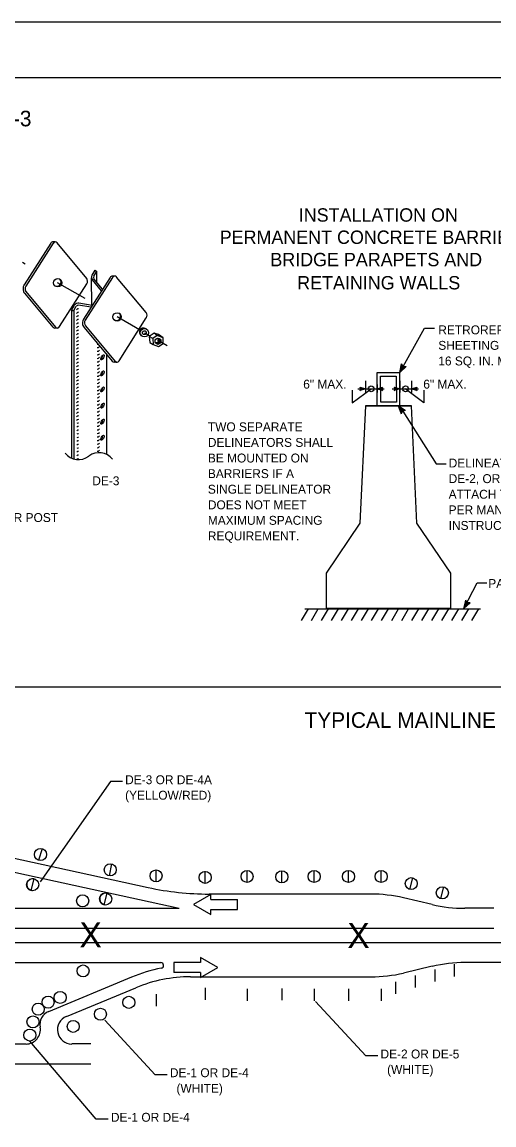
# Model space of a CAD drawing. Extents: x -0.14 to 2.7, y -0.05 to 1.78.
# Drawn here: x 0.739 to 1.18, y 0.749 to 1.781 of the extents above; entities that cross this region are included whole.
import ezdxf

# ---------------------------------------------------------------- set-up
doc = ezdxf.new("R2010")
doc.units = 0
for name, color, linetype in [('BDR_Outer_Perimeter', 7, 'Continuous'), ('BDR_Perimeter', 7, 'Continuous'), ('CT_CSHT_GeneralLabel', 7, 'Continuous')]:
    doc.layers.add(name, color=color, linetype=linetype)

msp = doc.modelspace()

# ---------------------------------------------------------------- linework, layer by layer
at = {"layer": 'BDR_Outer_Perimeter'}
msp.add_lwpolyline([(-0.1354, -0.0521), (2.6979, -0.0521), (2.6979, 1.7812), (-0.1354, 1.7812)], close=True, dxfattribs=at)
at = {"layer": 'BDR_Perimeter'}
msp.add_line((2.6458, 1.7292), (0, 1.7292), dxfattribs=at)
at = {"layer": 'CT_CSHT_GeneralLabel'}
for p, q in [((0.766, 1.5743), (0.7411, 1.5354)), ((0.7682, 1.5743), (0.7426, 1.5342)), ((0.7701, 1.5756), (0.7682, 1.5756)), ((0.7996, 1.5414), (0.7719, 1.5747)), ((0.7395, 1.5565), (0.742, 1.555)), ((0.8073, 1.5492), (0.8045, 1.5444)), ((0.8089, 1.5482), (0.8061, 1.5434)), ((0.8073, 1.5492), (0.8089, 1.5482)), ((0.8089, 1.5482), (0.8089, 1.5383)), ((0.7719, 1.5377), (0.7978, 1.5228)), ((0.8215, 1.5423), (0.7967, 1.5034)), ((0.8237, 1.5423), (0.7982, 1.5022)), ((0.8043, 1.5162), (0.804, 1.542)), ((0.8133, 1.5298), (0.8049, 1.54)), ((0.8143, 1.5315), (0.8063, 1.5411)), ((0.8256, 1.5436), (0.8238, 1.5436)), ((0.8552, 1.5094), (0.8274, 1.5427)), ((0.7414, 1.5277), (0.7679, 1.4959)), ((0.7428, 1.5291), (0.7705, 1.4958)), ((0.7742, 1.4963), (0.7998, 1.5363)), ((0.8046, 1.5161), (0.7923, 1.5182)), ((0.7855, 1.5115), (0.7883, 1.5163)), ((0.7855, 1.5115), (0.7877, 1.5115)), ((0.7855, 1.5115), (0.7855, 1.3733)), ((0.7877, 1.5115), (0.7899, 1.5154)), ((0.7877, 1.5115), (0.7877, 1.3725)), ((0.8035, 1.5144), (0.792, 1.5164)), ((0.7984, 1.4971), (0.8261, 1.4638)), ((0.8489, 1.4933), (0.828, 1.5054)), ((0.8298, 1.4643), (0.8553, 1.5044)), ((0.7722, 1.4949), (0.7698, 1.495)), ((0.797, 1.4957), (0.8234, 1.4639)), ((0.8535, 1.4906), (0.858, 1.488)), ((0.8627, 1.4901), (0.8581, 1.487)), ((0.8581, 1.487), (0.8585, 1.4815)), ((0.8614, 1.4851), (0.8581, 1.487)), ((0.8668, 1.4889), (0.8627, 1.4901)), ((0.8655, 1.488), (0.8627, 1.4901)), ((0.8709, 1.4858), (0.8668, 1.4889)), ((0.8585, 1.4815), (0.8617, 1.4796)), ((0.8749, 1.4783), (0.8659, 1.4835)), ((0.818, 1.4701), (0.818, 1.3769)), ((0.8277, 1.4629), (0.8254, 1.463)), ((1.0921, 1.4535), (1.0936, 1.4614)), ((1.0921, 1.4535), (1.0939, 1.4607)), ((1.0921, 1.4535), (1.0943, 1.4603)), ((1.0921, 1.4535), (1.0949, 1.4597)), ((1.0921, 1.4535), (1.0954, 1.4594)), ((1.0921, 1.4535), (1.0958, 1.4592)), ((1.0921, 1.4535), (1.0964, 1.459)), ((1.098, 1.4589), (1.0921, 1.4535)), ((1.0921, 1.4535), (1.097, 1.4589)), ((1.06, 1.4457), (1.06, 1.4347)), ((1.071, 1.4535), (1.0921, 1.4535)), ((1.071, 1.4222), (1.071, 1.4535)), ((1.0921, 1.4222), (1.0921, 1.4535)), ((1.0921, 1.4457), (1.0921, 1.4347)), ((1.103, 1.4457), (1.103, 1.4347)), ((1.0529, 1.438), (1.0776, 1.438)), ((1.055, 1.4397), (1.06, 1.438)), ((1.06, 1.438), (1.055, 1.4364)), ((1.06, 1.438), (1.0552, 1.4368)), ((1.06, 1.438), (1.0553, 1.4391)), ((1.06, 1.438), (1.0554, 1.4372)), ((1.06, 1.438), (1.0555, 1.4387)), ((1.06, 1.438), (1.0555, 1.4384)), ((1.06, 1.438), (1.0555, 1.438)), ((1.06, 1.438), (1.0555, 1.4376)), ((1.071, 1.442), (1.071, 1.4347)), ((1.071, 1.438), (1.076, 1.4397)), ((1.071, 1.438), (1.0757, 1.4393)), ((1.071, 1.438), (1.0756, 1.4389)), ((1.071, 1.438), (1.0754, 1.4384)), ((1.076, 1.4364), (1.071, 1.438)), ((1.071, 1.438), (1.0754, 1.438)), ((1.071, 1.438), (1.0755, 1.4373)), ((1.071, 1.438), (1.0756, 1.4369)), ((1.071, 1.438), (1.0754, 1.4377)), ((1.085, 1.438), (1.1097, 1.438)), ((1.087, 1.4397), (1.0921, 1.438)), ((1.0921, 1.438), (1.087, 1.4364)), ((1.0921, 1.438), (1.0873, 1.4368)), ((1.0921, 1.438), (1.0874, 1.4391)), ((1.0921, 1.438), (1.0875, 1.4387)), ((1.0921, 1.438), (1.0875, 1.4372)), ((1.0921, 1.438), (1.0876, 1.4384)), ((1.0921, 1.438), (1.0876, 1.438)), ((1.0921, 1.438), (1.0876, 1.4376)), ((1.103, 1.438), (1.1081, 1.4397)), ((1.103, 1.438), (1.1078, 1.4393)), ((1.103, 1.438), (1.1076, 1.4389)), ((1.103, 1.438), (1.1075, 1.4384)), ((1.1081, 1.4364), (1.103, 1.438)), ((1.103, 1.438), (1.1075, 1.438)), ((1.103, 1.438), (1.1076, 1.4373)), ((1.103, 1.438), (1.1077, 1.4369)), ((1.103, 1.438), (1.1075, 1.4377)), ((1.06, 1.4222), (1.0548, 1.3125)), ((1.103, 1.4222), (1.06, 1.4222)), ((1.06, 1.4222), (1.103, 1.4222)), ((1.103, 1.4222), (1.06, 1.4222)), ((1.071, 1.4222), (1.0921, 1.4222)), ((1.0973, 1.4179), (1.0905, 1.4223)), ((1.0905, 1.4223), (1.0933, 1.4147)), ((1.0905, 1.4223), (1.0948, 1.417)), ((1.0905, 1.4223), (1.0957, 1.4175)), ((1.0905, 1.4223), (1.0939, 1.416)), ((1.0905, 1.4223), (1.0963, 1.4177)), ((1.0905, 1.4223), (1.0952, 1.4172)), ((1.0905, 1.4223), (1.0943, 1.4166)), ((1.0905, 1.4223), (1.0936, 1.4154)), ((1.1082, 1.3125), (1.103, 1.4222)), ((1.0548, 1.3125), (1.0234, 1.2657)), ((1.1397, 1.2657), (1.1082, 1.3125)), ((1.0234, 1.2657), (1.0234, 1.233)), ((1.1397, 1.233), (1.1397, 1.2657)), ((1.1534, 1.2405), (1.1519, 1.2326)), ((1.1519, 1.2326), (1.1539, 1.2396)), ((1.1519, 1.2326), (1.1543, 1.2392)), ((1.1519, 1.2326), (1.1548, 1.2388)), ((1.1519, 1.2326), (1.1552, 1.2385)), ((1.1519, 1.2326), (1.1557, 1.2382)), ((1.0002, 1.2212), (1.0067, 1.2324)), ((1.0033, 1.2324), (1.1675, 1.2324)), ((1.0096, 1.2212), (1.016, 1.2324)), ((1.019, 1.2212), (1.0254, 1.2324)), ((1.0234, 1.233), (1.1397, 1.233)), ((1.0283, 1.2212), (1.0348, 1.2324)), ((1.0377, 1.2212), (1.0442, 1.2324)), ((1.0471, 1.2212), (1.0535, 1.2324)), ((1.0565, 1.2212), (1.0629, 1.2324)), ((1.0658, 1.2212), (1.0723, 1.2324)), ((1.0752, 1.2212), (1.0817, 1.2324)), ((1.0846, 1.2212), (1.091, 1.2324)), ((1.094, 1.2212), (1.1004, 1.2324)), ((1.1033, 1.2212), (1.1098, 1.2324)), ((1.1127, 1.2212), (1.1192, 1.2324)), ((1.1221, 1.2212), (1.1285, 1.2324)), ((1.1315, 1.2212), (1.1379, 1.2324)), ((1.1408, 1.2212), (1.1473, 1.2324)), ((1.1502, 1.2212), (1.1567, 1.2324)), ((1.1519, 1.2326), (1.1565, 1.2381)), ((1.1519, 1.2326), (1.1579, 1.238)), ((1.1519, 1.2326), (1.1571, 1.238)), ((1.1596, 1.2212), (1.166, 1.2324)), ((2.6458, 1.1591), (0, 1.1591)), ((0.8217, 1.0706), (0.756, 0.9767)), ((0.833, 1.0706), (0.8217, 1.0706)), ((0.6272, 1.0218), (0.8571, 0.9716)), ((0.6308, 1.0078), (0.886, 0.9521)), ((0.758, 1.0078), (0.7547, 0.997)), ((0.8227, 0.9936), (0.8205, 0.9826)), ((0.8644, 0.9768), (0.8644, 0.988)), ((0.9103, 0.9754), (0.9103, 0.9867)), ((0.9494, 0.9763), (0.9494, 0.9875)), ((0.9819, 0.9759), (0.9819, 0.9871)), ((1.0121, 0.9763), (1.0121, 0.9875)), ((1.0442, 0.9763), (1.0442, 0.9875)), ((1.0747, 0.9763), (1.0747, 0.9875)), ((1.1014, 0.9697), (1.1043, 0.9806)), ((0.7477, 0.9688), (0.7505, 0.9797)), ((1.1304, 0.9612), (1.1334, 0.9721)), ((0.8159, 0.9553), (0.8187, 0.9662)), ((0.914, 0.9655), (1.0651, 0.9655)), ((0.9157, 0.9602), (0.9406, 0.9602)), ((0.9406, 0.951), (0.9406, 0.9602)), ((1.1224, 0.9556), (1.0956, 0.9619)), ((0.6263, 0.9521), (0.886, 0.9521)), ((0.9157, 0.951), (0.9406, 0.951)), ((1.1801, 0.9521), (1.1529, 0.9521)), ((0.6263, 0.9334), (1.1801, 0.9334)), ((0.6263, 0.9201), (1.3171, 0.9201)), ((0.6263, 0.9014), (0.8688, 0.9014)), ((0.8809, 0.9013), (0.8809, 0.8921)), ((0.9058, 0.9013), (0.8809, 0.9013)), ((1.1225, 0.8978), (1.0957, 0.8915)), ((1.143, 0.8997), (1.143, 0.8884)), ((1.3164, 0.9014), (1.153, 0.9014)), ((0.7641, 0.8556), (0.8419, 0.8879)), ((0.9058, 0.8921), (0.8809, 0.8921)), ((0.8967, 0.888), (1.0652, 0.888)), ((1.1065, 0.8892), (1.1065, 0.8779)), ((1.1248, 0.8949), (1.1248, 0.8836)), ((0.7806, 0.8509), (0.8455, 0.8778)), ((0.9103, 0.8777), (0.9103, 0.8664)), ((0.9819, 0.8772), (0.9819, 0.866)), ((1.0882, 0.8833), (1.0882, 0.8721)), ((0.8644, 0.8718), (0.8644, 0.8606)), ((0.9494, 0.8768), (0.9494, 0.8656)), ((1.0121, 0.8768), (1.0121, 0.8656)), ((1.0442, 0.8768), (1.0442, 0.8656)), ((1.0747, 0.8768), (1.0747, 0.8656)), ((1.0604, 0.814), (1.0135, 0.865)), ((0.8636, 0.7964), (0.8166, 0.8475)), ((0.8085, 0.7547), (0.7465, 0.8279)), ((0.629, 0.8252), (0.7429, 0.8252)), ((0.8033, 0.8252), (0.7857, 0.8252)), ((0.629, 0.8065), (0.8033, 0.8065)), ((1.0717, 0.814), (1.0604, 0.814)), ((0.8749, 0.7964), (0.8636, 0.7964)), ((0.8198, 0.7547), (0.8085, 0.7547))]:
    msp.add_line(p, q, dxfattribs=at)
for points in [[(0.8655, 1.488), (0.8614, 1.4851), (0.8617, 1.4796), (0.8667, 1.4778), (0.8709, 1.4806), (0.8709, 1.4858)], [(1.0741, 1.4501), (1.0889, 1.4501), (1.0892, 1.4256), (1.0744, 1.4256)]]:
    msp.add_lwpolyline(points, close=True, dxfattribs=at)
for points in [[(1.0921, 1.4535), (1.1151, 1.4949), (1.1246, 1.4949)], [(1.0477, 1.4369), (1.0477, 1.4249), (1.0653, 1.438)], [(1.1147, 1.4369), (1.1147, 1.4249), (1.0973, 1.438)], [(1.0951, 1.4171), (1.1261, 1.368), (1.1355, 1.368)], [(1.1519, 1.2326), (1.1643, 1.2567), (1.1736, 1.2567)], [(0.9157, 0.9602), (0.9157, 0.9651), (0.8994, 0.9557), (0.9157, 0.9462), (0.9157, 0.951)], [(0.9058, 0.8921), (0.9058, 0.8872), (0.9221, 0.8966), (0.9058, 0.9061), (0.9058, 0.9013)]]:
    msp.add_lwpolyline(points, dxfattribs=at)
for centre, radius in [((0.7725, 1.5373), 0.00392), ((0.828, 1.5054), 0.00392), ((0.8535, 1.4906), 0.00392), ((0.8535, 1.4906), 0.00179), ((0.8662, 1.4827), 0.00276), ((1.0654, 1.4381), 0.00275), ((1.0975, 1.4381), 0.00275), ((0.7564, 1.0024), 0.00563), ((0.8216, 0.9881), 0.00563), ((0.8644, 0.9824), 0.00563), ((0.9103, 0.981), 0.00563), ((0.9494, 0.9819), 0.00563), ((0.9819, 0.9815), 0.00563), ((1.0121, 0.9819), 0.00563), ((1.0442, 0.9819), 0.00563), ((1.0747, 0.9819), 0.00563), ((1.1029, 0.9752), 0.00563), ((0.7491, 0.9742), 0.00563), ((1.1319, 0.9666), 0.00563), ((0.7958, 0.9591), 0.00563), ((0.8173, 0.9608), 0.00563), ((0.7962, 0.8935), 0.00563), ((0.7635, 0.8643), 0.00563), ((0.7748, 0.8687), 0.00563), ((0.839, 0.8641), 0.00563), ((0.7543, 0.8577), 0.00563), ((0.8124, 0.853), 0.00563), ((0.7494, 0.8458), 0.00563), ((0.787, 0.8416), 0.00563), ((0.7465, 0.8335), 0.00563)]:
    msp.add_circle(centre, radius, dxfattribs=at)
for centre, radius, start, end in [((0.7717, 1.5379), 0.00392, 241.1632, 46.9248), ((0.8079, 1.5424), 0.00388, 150, 219.5791), ((0.8079, 1.5424), 0.00201, 150, 219.5791), ((0.7917, 1.5144), 0.00389, 80.4209, 150), ((0.7917, 1.5144), 0.00201, 80.4209, 150), ((0.7917, 1.511), 0.00201, 80.4209, 150), ((0.7917, 1.5077), 0.00201, 80.4209, 150), ((0.8274, 1.5058), 0.00392, 244.0349, 52.7972), ((0.7917, 1.5043), 0.00201, 80.4209, 150), ((0.7917, 1.501), 0.00201, 80.4209, 150), ((0.7917, 1.4977), 0.00201, 80.4209, 150), ((0.7917, 1.4943), 0.00201, 80.4209, 150), ((0.7917, 1.491), 0.00201, 80.4209, 150), ((0.7917, 1.4876), 0.00201, 80.4209, 150), ((0.7917, 1.4843), 0.00201, 80.4209, 150), ((0.8527, 1.4912), 0.0038, 49.6386, 235.0895), ((0.7917, 1.481), 0.00201, 80.4209, 150), ((0.7917, 1.4776), 0.00201, 80.4209, 150), ((0.7917, 1.4743), 0.00201, 80.4209, 150), ((0.8097, 1.482), 0.00201, 260.3142, 281.5975), ((0.8097, 1.4786), 0.00201, 260.3142, 330), ((0.8648, 1.4835), 0.00215, 235.7802, 63.4086), ((0.8648, 1.4835), 0.00263, 252.0191, 47.1698), ((0.8648, 1.4835), 0.00309, 265.5043, 32.6269), ((0.8648, 1.4835), 0.00351, 279.7939, 19.395), ((0.8648, 1.4835), 0.0039, 294.054, 5.1349), ((0.7917, 1.4709), 0.00201, 80.4209, 150), ((0.7917, 1.4676), 0.00201, 80.4209, 150), ((0.7917, 1.4642), 0.00201, 80.4209, 150), ((0.8097, 1.4753), 0.00201, 260.3142, 330), ((0.8097, 1.4719), 0.00201, 260.3142, 330), ((0.8097, 1.4686), 0.00201, 260.3142, 330), ((0.8055, 1.4701), 0.00903, 328.1083, 355.1481), ((0.7917, 1.4609), 0.00201, 80.4209, 150), ((0.7917, 1.4576), 0.00201, 80.4209, 150), ((0.7917, 1.4542), 0.00201, 80.4209, 150), ((0.8097, 1.4652), 0.00201, 260.3142, 330), ((0.8097, 1.4619), 0.00201, 260.3142, 330), ((0.8097, 1.4586), 0.00201, 260.3142, 330), ((1.0974, 1.4631), 0.00419, 203.2754, 278.477), ((0.7917, 1.4509), 0.00201, 80.4209, 150), ((0.7917, 1.4475), 0.00201, 80.4209, 150), ((0.7917, 1.4442), 0.00201, 80.4209, 150), ((0.8097, 1.4552), 0.00201, 260.3142, 330), ((0.8097, 1.4519), 0.00201, 260.3142, 330), ((0.8097, 1.4485), 0.00201, 260.3142, 330), ((0.8055, 1.455), 0.00903, 328.1083, 355.1481), ((0.7917, 1.4409), 0.00201, 80.4209, 150), ((0.7917, 1.4375), 0.00201, 80.4209, 150), ((0.7917, 1.4342), 0.00201, 80.4209, 150), ((0.8097, 1.4452), 0.00201, 260.3142, 330), ((0.8097, 1.4418), 0.00201, 260.3142, 330), ((0.8097, 1.4385), 0.00201, 260.3142, 330), ((0.8055, 1.44), 0.00903, 328.1083, 355.1481), ((1.0528, 1.438), 0.00274, 322.3992, 37.6008), ((1.0781, 1.438), 0.00274, 142.3992, 217.6008), ((1.0849, 1.438), 0.00274, 322.3992, 37.6008), ((1.1102, 1.438), 0.00274, 142.3992, 217.6008), ((0.7917, 1.4308), 0.00201, 80.4209, 150), ((0.7917, 1.4275), 0.00201, 80.4209, 150), ((0.7917, 1.4241), 0.00201, 80.4209, 150), ((0.8097, 1.4352), 0.00201, 260.3142, 330), ((0.8097, 1.4318), 0.00201, 260.3142, 330), ((0.8097, 1.4285), 0.00201, 260.3142, 330), ((0.8097, 1.4251), 0.00201, 260.3142, 330), ((0.8055, 1.4249), 0.00903, 328.1083, 355.1481), ((0.7917, 1.4208), 0.00201, 80.4209, 150), ((0.7917, 1.4175), 0.00201, 80.4209, 150), ((0.7917, 1.4141), 0.00201, 80.4209, 150), ((0.8097, 1.4218), 0.00201, 260.3142, 330), ((0.8097, 1.4185), 0.00201, 260.3142, 330), ((0.8097, 1.4151), 0.00201, 260.3142, 330), ((1.0974, 1.4137), 0.00419, 90.896, 166.0976), ((0.7917, 1.4108), 0.00201, 80.4209, 150), ((0.7917, 1.4074), 0.00201, 80.4209, 150), ((0.7917, 1.4041), 0.00201, 80.4209, 130.6073), ((0.8097, 1.4118), 0.00201, 260.3142, 330), ((0.8097, 1.4084), 0.00201, 260.3142, 330), ((0.8097, 1.4051), 0.00201, 260.3142, 330), ((0.8055, 1.4098), 0.00903, 328.1083, 355.1481), ((0.7917, 1.4008), 0.00201, 80.4209, 130.6073), ((0.7917, 1.3974), 0.00201, 80.4209, 130.6073), ((0.7917, 1.3941), 0.00201, 80.4209, 130.6073), ((0.8097, 1.4017), 0.00201, 260.3142, 330), ((0.8097, 1.3984), 0.00201, 260.3142, 330), ((0.8097, 1.3951), 0.00201, 260.3142, 330), ((0.8055, 1.3948), 0.00903, 328.1083, 355.1481), ((0.7917, 1.3907), 0.00201, 80.4209, 130.6073), ((0.7917, 1.3874), 0.00201, 80.4209, 130.6073), ((0.7917, 1.384), 0.00201, 80.4209, 130.6073), ((0.7917, 1.3807), 0.00201, 80.4209, 130.6073), ((0.8097, 1.3917), 0.00201, 260.3142, 330), ((0.8097, 1.3884), 0.00201, 260.3142, 330), ((0.8097, 1.385), 0.00201, 260.3142, 330), ((0.792, 1.3878), 0.0159, 218.1508, 307.2188), ((0.7917, 1.3774), 0.00201, 80.4209, 130.6073), ((0.7917, 1.374), 0.00201, 80.4209, 130.6073), ((0.7917, 1.3707), 0.00201, 80.4209, 130.6073), ((0.8112, 1.3625), 0.0159, 38.1508, 127.2188), ((0.8097, 1.3817), 0.00201, 260.3142, 330), ((1.1573, 1.2422), 0.00419, 203.2751, 278.4768), ((0.7491, 0.9742), 0.00563, 75.3847, 255.3847), ((0.914, 1.2325), 0.2671, 257.685, 270), ((0.8173, 0.9608), 0.00563, 75.3847, 255.3847), ((1.0651, 0.8319), 0.1335, 76.7991, 90), ((1.1529, 1.0856), 0.1335, 256.7915, 270), ((0.8688, 0.8987), 0.00267, 280.9425, 90), ((1.153, 0.7678), 0.1335, 90, 103.2012), ((0.8967, 0.7545), 0.1442, 100.9425, 112.5473), ((0.8967, 0.7545), 0.1335, 90, 112.5473), ((1.0652, 1.0215), 0.1335, 270, 283.2219), ((0.7692, 0.8432), 0.0134, 112.549, 190.1797), ((0.7857, 0.8385), 0.0134, 112.549, 270), ((0.7429, 0.8385), 0.0134, 270, 10.1797)]:
    msp.add_arc(centre, radius, start, end, dxfattribs=at)
for centre, major_axis, ratio, start_param, end_param in [((0.7682, 1.5726), (0.00005, 0.00301), 0.9, 6.283185, 7.256403), ((0.7701, 1.5719), (0.00027, 0.0036), 0.720779, 5.644935, 7.215606), ((0.7978, 1.5386), (0.00027, 0.0036), 0.720779, 4.074013, 5.644576), ((0.8237, 1.5406), (0.00005, 0.00301), 0.9, 6.283185, 7.256403), ((0.8257, 1.54), (0.00027, 0.0036), 0.720779, 5.644935, 7.215606), ((0.7446, 1.5319), (0.00038, 0.00568), 0.786721, 0.922053, 2.492942), ((0.7446, 1.5319), (0.00027, 0.0036), 0.720779, 0.93242, 2.503309), ((0.8534, 1.5067), (0.00027, 0.0036), 0.720779, 4.074013, 5.644576), ((0.7723, 1.4986), (-0.00027, -0.0036), 0.720779, 5.644632, 7.215486), ((0.8001, 1.4999), (0.00038, 0.00568), 0.786721, 0.922053, 2.492942), ((0.8001, 1.4999), (0.00027, 0.0036), 0.720779, 0.93242, 2.503309), ((0.7699, 1.498), (-0.00005, -0.00301), 0.9, 5.476378, 6.283185), ((0.8254, 1.466), (-0.00005, -0.00301), 0.9, 5.476378, 6.283185), ((0.8279, 1.4666), (-0.00027, -0.0036), 0.720779, 5.644632, 7.215486)]:
    msp.add_ellipse(centre, major_axis=major_axis, ratio=ratio, start_param=start_param, end_param=end_param, dxfattribs=at)
for centre in [(0.8144, 1.4676), (0.8144, 1.4525), (0.8144, 1.4375), (0.8144, 1.4224), (0.8144, 1.4074), (0.8144, 1.3923)]:
    msp.add_ellipse(centre, major_axis=(0.0013, 0.00229), ratio=0.403108, dxfattribs=at)

# ---------------------------------------------------------------- texts
for s, height, p in [('DELINEATORS DE-1, DE-2, DE-3', 0.014583, (0.45, 1.6837)), ('INSTALLATION ON', 0.0125, (0.9978, 1.5945)), ('PERMANENT CONCRETE BARRIER,', 0.0125, (0.9239, 1.5737)), ('BRIDGE PARAPETS AND', 0.0125, (0.9712, 1.5528)), ('RETAINING WALLS', 0.0125, (0.9963, 1.5311)), ('RETROREFLECTIVE', 0.008333, (1.1281, 1.4891)), ('SHEETING', 0.00833, (1.1281, 1.4746)), ('16 SQ. IN. MIN.', 0.008333, (1.1281, 1.46)), ('6" MAX.', 0.00833, (1.0019, 1.4383)), ('6" MAX.', 0.00833, (1.1141, 1.4383)), ('TWO SEPARATE', 0.008333, (0.9128, 1.3984)), ('DELINEATORS SHALL', 0.008333, (0.9128, 1.3838)), ('BE MOUNTED ON', 0.008333, (0.9128, 1.3692)), ('DELINEATOR DE-1, ', 0.008333, (1.1378, 1.3645)), ('BARRIERS IF A ', 0.008333, (0.9128, 1.3546)), ('DE-3', 0.00833, (0.8048, 1.3479)), ('DE-2, OR DE-3', 0.008333, (1.1378, 1.3499)), ('SINGLE DELINEATOR', 0.008333, (0.9128, 1.34)), ('ATTACH TO CONCRETE', 0.008333, (1.1378, 1.3353)), ('DOES NOT MEET', 0.008333, (0.9128, 1.3254)), ('TYPICAL METAL DELINEATOR POST', 0.008333, (0.5784, 1.3135)), ("PER MANUFACTURER'S", 0.008333, (1.1378, 1.3207)), ('MAXIMUM SPACING', 0.008333, (0.9128, 1.3109)), ('INSTRUCTIONS', 0.008333, (1.1378, 1.3061)), ('REQUIREMENT.', 0.008333, (0.9128, 1.2963)), ('PAVEMENT', 0.00833, (1.1748, 1.2518)), ('TYPICAL MAINLINE & INTERCHANGE DELINEATION', 0.014583, (1.0031, 1.1209)), ('DE-3 OR DE-4A', 0.008333, (0.8355, 1.0682)), ('(YELLOW/RED)', 0.008333, (0.8355, 1.0537)), ('X', 0.0235, (0.7928, 0.9155)), ('X', 0.0235, (1.0431, 0.9149)), ('DE-2 OR DE-5', 0.008333, (1.0741, 0.8116)), ('  (WHITE)', 0.00833, (1.0741, 0.7971)), ('DE-1 OR DE-4', 0.008333, (0.8773, 0.7941)), ('  (WHITE)', 0.00833, (0.8773, 0.7795)), ('DE-1 OR DE-4', 0.008333, (0.8222, 0.7524))]:
    msp.add_text(s, height=height, dxfattribs=at).set_placement(p)

doc.saveas('drawing.dxf')
